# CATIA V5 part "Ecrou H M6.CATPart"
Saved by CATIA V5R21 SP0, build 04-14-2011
Part number: Ecrou H M6
Material "Acier": density 7860 kg/m3, Young's modulus 2e+11 Pa, Poisson ratio 0.266, thermal expansion 1.17e-05 1/K
Bounding box of the stored display mesh (mm): x -4 to 4, y -4.619 to 4.619, z 0 to 3
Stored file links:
  C:\Users\Olivier\Desktop\redaction CATIA (local)\pompe à moteur de ventilation refait\Ecrou H M6.CATPart
  C:\Program Files\Dassault Systemes\B21\win_b64\startup\materials\French\Catalog.CATMaterial
  C:\Program Files\Dassault Systemes\B21\win_b64\resources\graphic\figures\CATIA_EnvironmentMap_Satin_512x512.jpg
  C:\Users\Olivier\Desktop\redaction CATIA (local)\pompe à moteur de ventilation refait\Pompe_a_moteur_de_ventilation.CATProduct
  C:\Users\Olivier\Desktop\redaction CATIA (local)\pompe à moteur de ventilation refait\Ecrou a collerette M5.CATPart
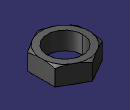
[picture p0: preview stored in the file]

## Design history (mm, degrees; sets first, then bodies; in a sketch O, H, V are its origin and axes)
Body1 (main body), material "Acier"
  Sketch1 on xy-plane, origin (0, 0, 0), H (1, 0, 0), V (0, 1, 0)
    circle A1 centre (0, 0) radius 3
    point P1 (4, -2.3094)
    point P2 (4, 2.3094)
    point P3 (0, 4.6188)
    point P4 (-4, 2.3094)
    point P5 (-4, -2.3094)
    point P6 (0, -4.6188)
    point P7 (4, 0)
    line L1 (4, -2.3094) -> (4, 2.3094)
    line L2 (4, 2.3094) -> (0, 4.6188)
    line L3 (0, 4.6188) -> (-4, 2.3094)
    line L4 (-4, 2.3094) -> (-4, -2.3094)
    line L5 (-4, -2.3094) -> (0, -4.6188)
    line L6 (0, -4.6188) -> (4, -2.3094)
    construction line L7 (0, 0) -> (4, 0)
    construction circle A2 centre (0, 0) radius 4.6188
    construction arc A3 centre (-4, -2.3094) radius 4.6188 from (-4, 2.3094) to (0, -4.6188) cw
    construction arc A4 centre (4, 2.3094) radius 4.6188 from (0, 4.6188) to (4, -2.3094) ccw
    distance L1 L4 = 8
    horizontal: L7 H
    coincidence: A2 P1, A2 P2, A2 P3, A2 P4, A2 P5, A2 P6, A3 O, A4 O
    midpoint: P7 L1
    parallelism: L1 L4
  Pad1: profile Sketch1, direction (0, 0, 1), length 3
  Sketch2 on yz-plane, origin (0, 0, 0), H (0, 1, 0), V (0, 0, 1)
    line L1 (3.8458, 3.1016) -> (4.7183, 2.6279)
    line L2 (4.7183, 2.6279) -> (4.7183, 3.1016)
    line L3 (4.7183, 3.1016) -> (3.8458, 3.1016)
    vertical: L2 V
    horizontal: L3 H
  Groove1: profile Sketch2, axis Sketch2.V, angle 360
